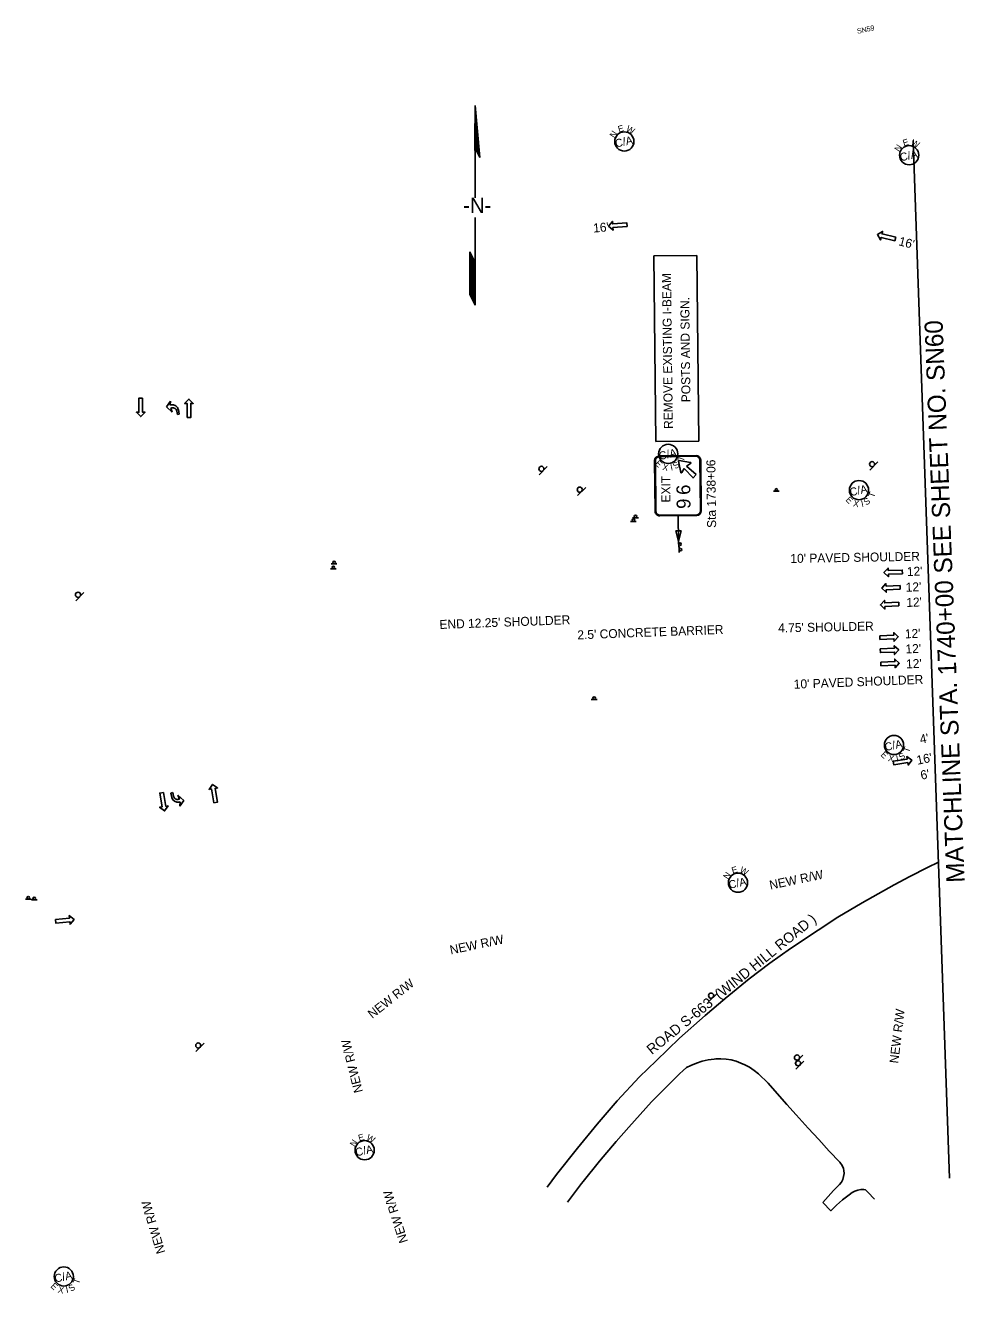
# Model space of a CAD drawing. Extents: x 1818895 to 1820505, y 1192175 to 1193276.
# Drawn here: x 1819771 to 1820505, y 1192285 to 1193276 of the extents above; entities that cross this region are included whole.
import ezdxf

# ---------------------------------------------------------------- set-up
doc = ezdxf.new("R2010")
doc.units = 0
for name, color, linetype in [('RD_EX_Road', 7, 'Continuous'), ('RD_PD_Final_LnLine', 7, 'Continuous'), ('RD_PD_Final_TX', 7, 'Continuous'), ('RD_PD_RW_TX', 7, 'Continuous'), ('RD_SHT_MatchLine', 7, 'Continuous'), ('RD_SHT_TX', 7, 'Continuous'), ('RD_Sketch1', 7, 'Continuous'), ('RD_Sketch10', 7, 'Continuous'), ('RD_Sketch8', 7, 'Continuous'), ('RD_TX_RoadID', 7, 'Continuous'), ('SN_P_Signs', 7, 'Continuous')]:
    doc.layers.add(name, color=color, linetype=linetype)

# ---------------------------------------------------------------- blocks, each defined once
blk = doc.blocks.new('SARRW2')
at = {"layer": 'RD_PD_Final_LnLine'}
blk.add_lwpolyline([(-12, 1.2), (-12, -1.2), (-2.83, -1.2), (-2.83, -2.83), (0, 0), (-2.83, 2.83), (-2.83, 1.2)], close=True, dxfattribs=at)

msp = doc.modelspace()

# ---------------------------------------------------------------- linework, layer by layer
at = {"layer": 'RD_EX_Road'}
for points in [[(1820484.41, 1192621.87), (1820475.7, 1192617.73), (1820461.93, 1192610.76), (1820449.62, 1192604.14), (1820424.85, 1192590.05), (1820405.76, 1192578.87), (1820390.26, 1192568.9), (1820368.89, 1192554.43), (1820352.53, 1192543.06), (1820336.56, 1192530.91), (1820317.8, 1192515.51), (1820302.07, 1192502.1), (1820281.98, 1192484.47), (1820263.81, 1192466.85), (1820250.89, 1192454.36), (1820233.54, 1192435.52), (1820217.85, 1192417.25), (1820202.37, 1192398.44), (1820186.16, 1192377.87), (1820178.79, 1192368.17)], [(1820394.01, 1192356.17), (1820402.48, 1192365.57), (1820407.1, 1192370.14), (1820408.49, 1192372.03), (1820409.56, 1192374.13), (1820410.26, 1192376.37), (1820410.57, 1192378.7), (1820410.49, 1192381.05), (1820410.18, 1192382.75), (1820409.15, 1192385.11), (1820407.3, 1192387.58), (1820399.03, 1192396.21), (1820390.87, 1192405.25), (1820382.59, 1192414.24), (1820373.24, 1192424.51), (1820366, 1192432.68), (1820358.3, 1192441.21), (1820351.26, 1192449.33), (1820343.71, 1192456.62), (1820340.36, 1192459.31), (1820336.79, 1192461.68), (1820333.01, 1192463.71), (1820330.09, 1192464.99), (1820326.32, 1192466.4), (1820322.43, 1192467.43), (1820318.46, 1192468.08), (1820314.45, 1192468.33), (1820310.43, 1192468.19), (1820309.29, 1192468.08), (1820304.54, 1192467.43), (1820299.87, 1192466.39), (1820295.3, 1192464.97), (1820290.86, 1192463.17), (1820287.66, 1192461.6), (1820285.04, 1192459.24), (1820282.11, 1192456.47), (1820266.01, 1192440.46), (1820260.34, 1192434.68), (1820242.5, 1192415.01), (1820232.74, 1192403.84), (1820219.64, 1192388.32), (1820206.85, 1192372.55), (1820205.55, 1192370.83), (1820194.76, 1192356.4)], [(1820434.4, 1192358.58), (1820429.19, 1192364.15), (1820427.47, 1192365.92), (1820426.15, 1192366.22), (1820423.72, 1192366.21), (1820421.33, 1192365.81), (1820419.03, 1192365.02), (1820416.89, 1192363.88), (1820414.46, 1192362.15), (1820409.51, 1192358.27), (1820404.81, 1192354.1), (1820400.39, 1192349.64), (1820394.01, 1192356.17)]]:
    msp.add_lwpolyline(points, dxfattribs=at)
at = {"layer": 'RD_PD_Final_LnLine'}
for p, q in [((1819884.59, 1192982.14), (1819881.41, 1192977.58)), ((1819884.59, 1192982.14), (1819881.41, 1192977.58)), ((1819884.42, 1192978.86), (1819884.59, 1192982.14)), ((1819884.42, 1192978.86), (1819884.59, 1192982.14)), ((1819881.41, 1192977.58), (1819886.07, 1192973.52)), ((1819881.41, 1192977.58), (1819886.07, 1192973.52)), ((1819885.26, 1192979.05), (1819884.42, 1192978.86)), ((1819885.26, 1192979.05), (1819884.42, 1192978.86)), ((1819884.91, 1192976.61), (1819885.75, 1192976.8)), ((1819884.91, 1192976.61), (1819885.75, 1192976.8)), ((1819886.07, 1192973.52), (1819884.91, 1192976.61)), ((1819886.07, 1192973.52), (1819884.91, 1192976.61)), ((1819889.54, 1192974.28), (1819890.14, 1192971.56)), ((1819889.54, 1192974.28), (1819890.14, 1192971.56)), ((1819890.14, 1192971.56), (1819891.54, 1192971.87)), ((1819890.14, 1192971.56), (1819891.54, 1192971.87)), ((1819890.14, 1192971.56), (1819890.14, 1192971.56)), ((1819890.14, 1192971.56), (1819890.14, 1192971.56)), ((1819891.54, 1192971.87), (1819890.77, 1192975.43)), ((1819891.54, 1192971.87), (1819890.77, 1192975.43)), ((1819886.43, 1192676.25), (1819885.02, 1192675.94)), ((1819886.43, 1192676.25), (1819885.02, 1192675.94)), ((1819885.02, 1192675.94), (1819885.8, 1192672.38)), ((1819885.02, 1192675.94), (1819885.8, 1192672.38)), ((1819887.02, 1192673.53), (1819886.43, 1192676.25)), ((1819886.43, 1192676.25), (1819886.43, 1192676.25)), ((1819887.02, 1192673.53), (1819886.43, 1192676.25)), ((1819886.43, 1192676.25), (1819886.43, 1192676.25)), ((1819895.15, 1192670.23), (1819890.49, 1192674.28)), ((1819890.49, 1192674.28), (1819891.66, 1192671.2)), ((1819895.15, 1192670.23), (1819890.49, 1192674.28)), ((1819890.49, 1192674.28), (1819891.66, 1192671.2)), ((1819891.66, 1192671.2), (1819890.81, 1192671.01)), ((1819891.66, 1192671.2), (1819890.81, 1192671.01)), ((1819891.31, 1192668.76), (1819892.15, 1192668.94)), ((1819891.31, 1192668.76), (1819892.15, 1192668.94)), ((1819891.98, 1192665.67), (1819895.15, 1192670.23)), ((1819891.98, 1192665.67), (1819895.15, 1192670.23)), ((1819892.15, 1192668.94), (1819891.98, 1192665.67)), ((1819892.15, 1192668.94), (1819891.98, 1192665.67))]:
    msp.add_line(p, q, dxfattribs=at)
for centre, radius, start, end in [((1819886.17, 1192974.43), 4.7, 12.28699, 101.12954), ((1819886.17, 1192974.43), 4.7, 12.28699, 101.12954), ((1819886.43, 1192973.7), 3.17, 10.56242, 102.32524), ((1819886.43, 1192973.7), 3.17, 10.56242, 102.32524), ((1819890.4, 1192673.38), 4.7, 192.28699, 281.12954), ((1819890.4, 1192673.38), 4.7, 192.28699, 281.12954), ((1819890.14, 1192674.11), 3.17, 190.56242, 282.32524), ((1819890.14, 1192674.11), 3.17, 190.56242, 282.32524)]:
    msp.add_arc(centre, radius, start, end, dxfattribs=at)
at = {"layer": 'RD_SHT_MatchLine'}
msp.add_line((1820464.64, 1193185.72), (1820493.06, 1192375.17), dxfattribs=at)
at = {"layer": 'RD_Sketch1'}
for p, q in [((1820122.42, 1193213.02), (1820122.21, 1193177.85)), ((1820126.15, 1193172.32), (1820122.42, 1193213.02)), ((1820122.42, 1193178.15), (1820122.42, 1193156.33)), ((1820122.72, 1193179.26), (1820126.15, 1193172.32)), ((1820122.42, 1193156.33), (1820122.42, 1193140.85)), ((1820122.42, 1193125.41), (1820122.42, 1193099.63)), ((1820118.43, 1193084.57), (1820118.43, 1193098.75)), ((1820118.43, 1193098.75), (1820122.42, 1193090.18)), ((1820122.42, 1193099.63), (1820122.42, 1193057.11)), ((1820118.43, 1193065.68), (1820118.43, 1193084.57)), ((1820122.42, 1193057.11), (1820118.43, 1193065.68))]:
    msp.add_line(p, q, dxfattribs=at)
for points in [[(1820122.43, 1193178.46), (1820122.43, 1193212.9)], [(1820122.53, 1193178.72), (1820122.53, 1193211.87)], [(1820122.62, 1193178.98), (1820122.62, 1193210.83)], [(1820122.71, 1193179.24), (1820122.71, 1193209.8)], [(1820122.81, 1193179.08), (1820122.81, 1193208.77)], [(1820122.9, 1193178.89), (1820122.9, 1193207.74)], [(1820122.34, 1193178.2), (1820122.34, 1193198.98)], [(1820123, 1193178.7), (1820123, 1193206.7)], [(1820123.09, 1193178.51), (1820123.09, 1193205.67)], [(1820123.19, 1193178.32), (1820123.19, 1193204.64)], [(1820123.28, 1193178.13), (1820123.28, 1193203.61)], [(1820123.38, 1193177.93), (1820123.38, 1193202.57)], [(1820123.47, 1193177.74), (1820123.47, 1193201.54)], [(1820123.57, 1193177.55), (1820123.57, 1193200.51)], [(1820123.66, 1193177.36), (1820123.66, 1193199.48)], [(1820123.75, 1193177.17), (1820123.75, 1193198.44)], [(1820123.85, 1193176.98), (1820123.85, 1193197.41)], [(1820123.94, 1193176.78), (1820123.94, 1193196.38)], [(1820124.04, 1193176.59), (1820124.04, 1193195.35)], [(1820124.13, 1193176.4), (1820124.13, 1193194.31)], [(1820124.23, 1193176.21), (1820124.23, 1193193.28)], [(1820124.32, 1193176.02), (1820124.32, 1193192.25)], [(1820124.42, 1193175.82), (1820124.42, 1193191.22)], [(1820124.51, 1193175.63), (1820124.51, 1193190.18)], [(1820124.6, 1193175.44), (1820124.6, 1193189.15)], [(1820124.7, 1193175.25), (1820124.7, 1193188.12)], [(1820122.24, 1193177.94), (1820122.24, 1193183.08)], [(1820124.79, 1193175.06), (1820124.79, 1193187.08)], [(1820124.89, 1193174.87), (1820124.89, 1193186.05)], [(1820124.98, 1193174.67), (1820124.98, 1193185.02)], [(1820125.08, 1193174.48), (1820125.08, 1193183.99)], [(1820125.17, 1193174.29), (1820125.17, 1193182.95)], [(1820125.27, 1193174.1), (1820125.27, 1193181.92)], [(1820125.36, 1193173.91), (1820125.36, 1193180.89)], [(1820125.46, 1193173.72), (1820125.46, 1193179.86)], [(1820125.55, 1193173.52), (1820125.55, 1193178.82)], [(1820125.64, 1193173.33), (1820125.64, 1193177.79)], [(1820125.74, 1193173.14), (1820125.74, 1193176.76)], [(1820125.83, 1193172.95), (1820125.83, 1193175.73)], [(1820125.93, 1193172.76), (1820125.93, 1193174.69)], [(1820126.02, 1193172.57), (1820126.02, 1193173.66)], [(1820126.12, 1193172.37), (1820126.12, 1193172.63)], [(1820118.5, 1193065.51), (1820118.5, 1193098.58)], [(1820118.6, 1193065.31), (1820118.6, 1193098.38)], [(1820118.69, 1193065.11), (1820118.69, 1193098.18)], [(1820118.79, 1193064.9), (1820118.79, 1193097.97)], [(1820118.88, 1193064.7), (1820118.88, 1193097.77)], [(1820118.98, 1193064.5), (1820118.98, 1193097.57)], [(1820119.07, 1193064.3), (1820119.07, 1193097.37)], [(1820119.17, 1193064.09), (1820119.17, 1193097.16)], [(1820119.26, 1193063.89), (1820119.26, 1193096.96)], [(1820119.35, 1193063.69), (1820119.35, 1193096.76)], [(1820119.45, 1193063.49), (1820119.45, 1193096.56)], [(1820119.54, 1193063.28), (1820119.54, 1193096.35)], [(1820119.64, 1193063.08), (1820119.64, 1193096.15)], [(1820119.73, 1193062.88), (1820119.73, 1193095.95)], [(1820119.83, 1193062.68), (1820119.83, 1193095.75)], [(1820119.92, 1193062.47), (1820119.92, 1193095.54)], [(1820120.02, 1193062.27), (1820120.02, 1193095.34)], [(1820120.11, 1193062.07), (1820120.11, 1193095.14)], [(1820120.2, 1193061.86), (1820120.2, 1193094.94)], [(1820120.3, 1193061.66), (1820120.3, 1193094.73)], [(1820120.39, 1193061.46), (1820120.39, 1193094.53)], [(1820120.49, 1193061.26), (1820120.49, 1193094.33)], [(1820120.58, 1193061.05), (1820120.58, 1193094.12)], [(1820120.68, 1193060.85), (1820120.68, 1193093.92)], [(1820120.77, 1193060.65), (1820120.77, 1193093.72)], [(1820120.87, 1193060.45), (1820120.87, 1193093.52)], [(1820120.96, 1193060.24), (1820120.96, 1193093.31)], [(1820121.06, 1193060.04), (1820121.06, 1193093.11)], [(1820121.15, 1193059.84), (1820121.15, 1193092.91)], [(1820121.24, 1193059.64), (1820121.24, 1193092.71)], [(1820121.34, 1193059.43), (1820121.34, 1193092.5)], [(1820121.43, 1193059.23), (1820121.43, 1193092.3)], [(1820121.53, 1193059.03), (1820121.53, 1193092.1)], [(1820121.62, 1193058.83), (1820121.62, 1193091.9)], [(1820121.72, 1193058.62), (1820121.72, 1193091.69)], [(1820121.81, 1193058.42), (1820121.81, 1193091.49)], [(1820121.91, 1193058.22), (1820121.91, 1193091.29)], [(1820122, 1193058.01), (1820122, 1193091.09)], [(1820122.09, 1193057.81), (1820122.09, 1193090.88)], [(1820122.19, 1193057.61), (1820122.19, 1193090.68)], [(1820122.28, 1193057.41), (1820122.28, 1193090.48)], [(1820122.38, 1193057.2), (1820122.38, 1193090.27)]]:
    msp.add_lwpolyline(points, dxfattribs=at)
at = {"layer": 'RD_Sketch10'}
for centre in [(1820239.05, 1193184.92), (1820461.44, 1193174.13), (1820327.76, 1192605.88), (1820036.25, 1192396.9)]:
    msp.add_circle(centre, 7.5, dxfattribs=at)
at = {"layer": 'RD_Sketch8'}
for centre in [(1820273.31, 1192940.83), (1820422.25, 1192912.55), (1820449.57, 1192713.46), (1819801.34, 1192298.31)]:
    msp.add_circle(centre, 7.5, dxfattribs=at)
at = {"layer": 'SN_P_Signs'}
for p, q in [((1820261.94, 1193095.49), (1820295.56, 1193095.89)), ((1820263.68, 1192950.48), (1820261.94, 1193095.49)), ((1820295.56, 1193095.89), (1820297.29, 1192950.88)), ((1820297.29, 1192950.88), (1820263.68, 1192950.48)), ((1820172.5, 1192924.54), (1820178.86, 1192930.9)), ((1820263.14, 1192895.96), (1820262.66, 1192935.55)), ((1820263.74, 1192895.96), (1820263.26, 1192935.56)), ((1820266.22, 1192939.2), (1820295.02, 1192939.54)), ((1820266.23, 1192938.6), (1820295.03, 1192938.94)), ((1820298.06, 1192935.98), (1820298.53, 1192896.38)), ((1820298.66, 1192935.98), (1820299.13, 1192896.39)), ((1820430.71, 1192928.2), (1820437.08, 1192934.57)), ((1820202.49, 1192908.27), (1820208.86, 1192914.64)), ((1820355.45, 1192911.68), (1820359.95, 1192911.68)), ((1820245.46, 1192891), (1820249.96, 1192891)), ((1820295.57, 1192893.34), (1820266.77, 1192893)), ((1820295.58, 1192892.74), (1820266.78, 1192892.4)), ((1820281.18, 1192892.57), (1820281.42, 1192872.53)), ((1820243.87, 1192888.03), (1820248.37, 1192888.03)), ((1820281.42, 1192872.53), (1820281.47, 1192868.03)), ((1820281.9, 1192868.27), (1820281.95, 1192863.77)), ((1820009.56, 1192851.15), (1820014.06, 1192851.15)), ((1820010.13, 1192854.99), (1820014.63, 1192854.99)), ((1819810.67, 1192826.15), (1819817.04, 1192832.51)), ((1820213.23, 1192749.09), (1820217.73, 1192749.09)), ((1819771.33, 1192593.13), (1819775.83, 1192593.13)), ((1819776, 1192592.53), (1819780.5, 1192592.53)), ((1820305.04, 1192513.03), (1820311.4, 1192519.4)), ((1819904.55, 1192474.1), (1819910.91, 1192480.47)), ((1820372.11, 1192464.71), (1820378.48, 1192471.07)), ((1820372.93, 1192460.21), (1820379.29, 1192466.57))]:
    msp.add_line(p, q, dxfattribs=at)
for points in [[(1820283.12, 1192926.4), (1820281.26, 1192935.24)], [(1820281.79, 1192935.77), (1820290.66, 1192934.13)], [(1820290.82, 1192933.3), (1820287.69, 1192931.37)], [(1820287.69, 1192931.37), (1820295.2, 1192924.67)], [(1820285.8, 1192929.44), (1820283.95, 1192926.27)], [(1820295.2, 1192924.67), (1820292.68, 1192922.1), (1820285.8, 1192929.44)]]:
    msp.add_lwpolyline(points, dxfattribs=at)
msp.add_lwpolyline([(1820283.37, 1192880.75), (1820281.42, 1192872.53), (1820279.27, 1192880.7)], close=True, dxfattribs=at)
for centre, radius in [((1820174.26, 1192929.16), 2), ((1820432.48, 1192932.83), 2), ((1820204.26, 1192912.9), 2), ((1820357.71, 1192912.7), 1), ((1820247.72, 1192892.01), 1), ((1820246.12, 1192889.05), 1), ((1820282.46, 1192870.28), 1), ((1820282.94, 1192866.02), 1), ((1820011.82, 1192852.17), 1), ((1820012.39, 1192856.01), 1), ((1819812.44, 1192830.78), 2), ((1820215.49, 1192750.1), 1), ((1819773.59, 1192594.14), 1), ((1819778.26, 1192593.54), 1), ((1820306.8, 1192517.66), 2), ((1819906.31, 1192478.73), 2), ((1820373.87, 1192469.33), 2), ((1820374.69, 1192464.83), 2)]:
    msp.add_circle(centre, radius, dxfattribs=at)
for centre, radius, start, end in [((1820266.26, 1192935.6), 3.6, 90.68445, 180.68445), ((1820266.26, 1192935.6), 3, 90.68445, 180.68445), ((1820281.7, 1192935.33), 0.45, 79.50655, 191.86235), ((1820290.58, 1192933.69), 0.45, 301.72235, 79.50655), ((1820295.06, 1192935.94), 3.6, 0.68445, 90.68445), ((1820295.06, 1192935.94), 3, 0.68445, 90.68445), ((1820283.56, 1192926.5), 0.45, 191.86235, 329.64655), ((1820266.74, 1192896), 3.6, 180.68445, 270.68445), ((1820266.74, 1192896), 3, 180.68445, 270.68445), ((1820295.53, 1192896.34), 3, 270.68445, 0.68445), ((1820295.53, 1192896.34), 3.6, 270.68445, 0.68445)]:
    msp.add_arc(centre, radius, start, end, dxfattribs=at)

# ---------------------------------------------------------------- block references
at = {"layer": 'RD_PD_Final_LnLine'}
for p, xscale, yscale, rotation in [((1820226.67, 1193118.82), 1.200000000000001, 1.200000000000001, -175.51587604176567), ((1820436.61, 1193112.09), 1.2000000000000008, 1.200000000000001, 166.60483210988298), ((1819861.43, 1192970.03), 1.200000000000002, 1.200000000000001, -89.94476898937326), ((1819899.01, 1192983.65), 1.2000000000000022, 1.2000000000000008, 90.05523101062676), ((1820441.76, 1192848.11), 1.200000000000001, 1.200000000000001, -177.70070663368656), ((1820440.06, 1192836), 1.200000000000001, 1.200000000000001, -177.70070663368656), ((1820439.03, 1192822.9), 1.200000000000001, 1.200000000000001, -177.70070663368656), ((1820452.92, 1192797.97), 1.2000000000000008, 1.2000000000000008, 2.2992933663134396), ((1820453.33, 1192787.66), 1.2000000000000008, 1.2000000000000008, 2.2992933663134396), ((1820453.75, 1192777.34), 1.2000000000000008, 1.2000000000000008, 2.2992933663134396), ((1820463.51, 1192701.63), 1.2000000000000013, 1.2000000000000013, 9.32061534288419), ((1819917.54, 1192682.71), 1.2000000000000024, 1.2000000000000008, 99.17562421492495), ((1819880.02, 1192661.96), 1.2000000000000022, 1.2000000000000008, -80.82437578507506), ((1819809.3, 1192577.13), 1.2000000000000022, 1.2000000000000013, 5.281491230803)]:
    msp.add_blockref('SARRW2', p, dxfattribs=dict(at, xscale=xscale, yscale=yscale, rotation=rotation))

# ---------------------------------------------------------------- texts
at = {"layer": 'RD_PD_Final_TX'}
for s, rotation, p in [("16'", 5.09604, (1820215.02, 1193113.69)), ("16'", 345.68852, (1820452.72, 1193103.91)), ("10' PAVED SHOULDER", 0.99063, (1820368.73, 1192855.64)), ("12'", 2.50593, (1820459.8, 1192845.37)), ("12'", 2.50593, (1820458.88, 1192833.13)), ("12'", 2.50593, (1820459.36, 1192821.24)), ("END 12.25' SHOULDER", 2.12406, (1820094.8, 1192804.07)), ("2.5' CONCRETE BARRIER", 2.17369, (1820202.49, 1192795.94)), ("4.75' SHOULDER", 1.13919, (1820359.21, 1192801.38)), ("12'", 2.50593, (1820458.22, 1192796.74)), ("12'", 2.50593, (1820458.7, 1192784.92)), ("12'", 2.50593, (1820459.17, 1192773.22)), ("10' PAVED SHOULDER", 2.17369, (1820371.46, 1192757.42)), ("4'", 11.63504, (1820470.45, 1192714.34)), ("16'", 11.63504, (1820467.98, 1192697.99)), ("6'", 11.63504, (1820471.03, 1192686.28))]:
    msp.add_text(s, height=7, rotation=rotation, dxfattribs=at).set_placement(p)
at = {"layer": 'RD_PD_RW_TX'}
for rotation, p in [(11.76548, (1820353.09, 1192600.47)), (11.76548, (1820103.55, 1192549.81)), (38.39887, (1820042.18, 1192499.44)), (83.10916, (1820452.89, 1192464.45)), (104.06428, (1820034.96, 1192442.71)), (106.55633, (1819880.71, 1192317.24)), (107.85567, (1820070.21, 1192325.7))]:
    msp.add_text('NEW R/W', height=7, rotation=rotation, dxfattribs=at).set_placement(p)
at = {"layer": 'RD_SHT_TX'}
for s, height, rotation, p in [('SN59', 4, 12.29893, (1820421.16, 1193268.95)), ('MATCHLINE STA. 1740+00 SEE SHEET NO. SN60', 14.1726, 92.25659, (1820504.8, 1192606.13))]:
    msp.add_text(s, height=height, rotation=rotation, dxfattribs=at).set_placement(p)
at = {"layer": 'RD_Sketch1'}
msp.add_text('-N-', height=11.811, rotation=0, dxfattribs=at).set_placement((1820113.23, 1193129.12))
at = {"layer": 'RD_Sketch10'}
for s, height, rotation, p in [('E', 5, 16.63198, (1820234.9, 1193191.91)), ('W', 5, 331.60154, (1820239.91, 1193193.25)), ('N', 5, 57.1687, (1820231.27, 1193187.15)), ('C/A', 6.25, 12.29893, (1820232.5, 1193180.14)), ('N', 5, 57.1687, (1820453.66, 1193176.36)), ('C/A', 6.25, 12.29893, (1820454.9, 1193169.35)), ('E', 5, 16.63198, (1820457.29, 1193181.11)), ('W', 5, 331.60154, (1820462.31, 1193182.46)), ('N', 5, 57.1687, (1820319.98, 1192608.11)), ('E', 5, 16.63198, (1820323.61, 1192612.86)), ('W', 5, 331.60154, (1820328.62, 1192614.21)), ('C/A', 6.25, 12.29893, (1820321.21, 1192601.1)), ('N', 5, 57.1687, (1820028.47, 1192399.13)), ('E', 5, 16.63198, (1820032.1, 1192403.89)), ('W', 5, 331.60154, (1820037.11, 1192405.23)), ('C/A', 6.25, 12.29893, (1820029.7, 1192392.12))]:
    msp.add_text(s, height=height, rotation=rotation, dxfattribs=at).set_placement(p)
at = {"layer": 'RD_Sketch8'}
for s, height, rotation, p in [('C/A', 6.25, 12.29893, (1820266.76, 1192936.04)), ('T', 5, 70.48408, (1820285.12, 1192934.49)), ('E', 5, 315.51017, (1820262.54, 1192932.83)), ('X', 5, 347.93955, (1820268.42, 1192928.32)), ('I', 5, 12.09955, (1820275.48, 1192927.74)), ('S', 5, 34.09137, (1820279.01, 1192928.69)), ('C/A', 6.25, 12.29893, (1820415.7, 1192907.76)), ('T', 5, 70.48408, (1820434.06, 1192906.21)), ('E', 5, 315.51017, (1820411.48, 1192904.55)), ('X', 5, 347.93955, (1820417.36, 1192900.04)), ('I', 5, 12.09955, (1820424.42, 1192899.46)), ('S', 5, 34.09137, (1820427.95, 1192900.41)), ('C/A', 6.25, 12.29893, (1820443.02, 1192708.68)), ('T', 5, 70.48408, (1820461.38, 1192707.12)), ('E', 5, 315.51017, (1820438.8, 1192705.46)), ('X', 5, 347.93955, (1820444.68, 1192700.95)), ('I', 5, 12.09955, (1820451.75, 1192700.37)), ('S', 5, 34.09137, (1820455.28, 1192701.32)), ('C/A', 6.25, 12.29893, (1819794.79, 1192293.53)), ('T', 5, 70.48408, (1819813.15, 1192291.97)), ('E', 5, 315.51017, (1819790.57, 1192290.31)), ('X', 5, 347.93955, (1819796.45, 1192285.8)), ('I', 5, 12.09955, (1819803.52, 1192285.22)), ('S', 5, 34.09137, (1819807.05, 1192286.17))]:
    msp.add_text(s, height=height, rotation=rotation, dxfattribs=at).set_placement(p)
at = {"layer": 'RD_TX_RoadID'}
msp.add_text('ROAD S-663  (WIND HILL ROAD )', height=8, rotation=39.07707, dxfattribs=at).set_placement((1820260.53, 1192471.17))
at = {"layer": 'SN_P_Signs'}
for s, height, rotation, p in [('REMOVE EXISTING I-BEAM', 6.9998, 90.68453, (1820276.92, 1192960.38)), ('POSTS AND SIGN.', 6.9998, 90.68453, (1820290.67, 1192981.26)), ('Sta 1738+06', 7, 90.68453, (1820310.71, 1192883.09)), ('EXIT', 7, 90.68445, (1820275.05, 1192902.9)), ('6', 10.8, 90.68445, (1820290.58, 1192908.88)), ('9', 10.8, 90.68445, (1820290.72, 1192897.96))]:
    msp.add_text(s, height=height, rotation=rotation, dxfattribs=at).set_placement(p)

doc.saveas('drawing.dxf')
